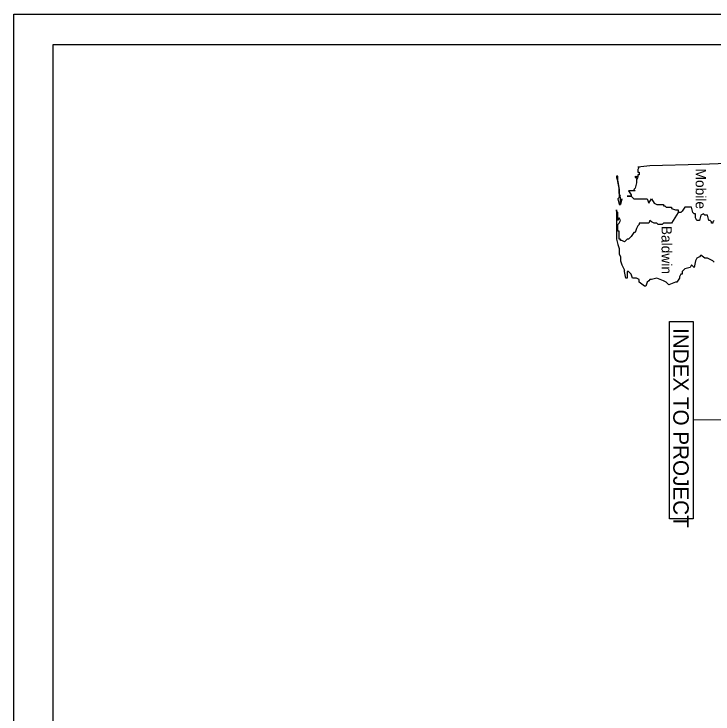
# Model space of a CAD drawing. Extents: x 0 to 0.917, y 0 to 0.708.
# Drawn here: x 0 to 0.3538, y 0.3542 to 0.7083 of the extents above; entities that cross this region are included whole.
import ezdxf

# ---------------------------------------------------------------- set-up
doc = ezdxf.new("R2010")
doc.units = 0
for name, color, linetype in [('ANNO-SHT', 7, 'Continuous'), ('ANNO-TXT', 7, 'Continuous'), ('SHT-BDR', 7, 'Continuous'), ('SHT-FENCE', 7, 'Continuous')]:
    doc.layers.add(name, color=color, linetype=linetype)

msp = doc.modelspace()

# ---------------------------------------------------------------- linework, layer by layer
at = {"layer": 'ANNO-SHT'}
msp.add_line((0.44418, 0.5033), (0.34372, 0.50284), dxfattribs=at)
for points in [[(0.31583, 0.63102), (0.31583, 0.63102), (0.31651, 0.63102), (0.31651, 0.63102), (0.31583, 0.62967), (0.31583, 0.62831), (0.31583, 0.62831), (0.31651, 0.62831), (0.31651, 0.62831), (0.31651, 0.62831), (0.31651, 0.62763), (0.31651, 0.62695), (0.31651, 0.62695), (0.31651, 0.62695), (0.31583, 0.62695), (0.31583, 0.62627), (0.31583, 0.62559), (0.31516, 0.62627), (0.31516, 0.62559), (0.31516, 0.62559), (0.31448, 0.62627), (0.31448, 0.62559), (0.31448, 0.62559), (0.31516, 0.62559), (0.31583, 0.62492), (0.31516, 0.62492), (0.31516, 0.62424), (0.31516, 0.62356), (0.31516, 0.62356), (0.31516, 0.62288), (0.31448, 0.62016), (0.3138, 0.61949), (0.31448, 0.61881), (0.31448, 0.61881), (0.31313, 0.61881), (0.31313, 0.61881), (0.31313, 0.61881), (0.31245, 0.61881), (0.3111, 0.61881), (0.3111, 0.61881), (0.31245, 0.61677), (0.31245, 0.61609), (0.3111, 0.61609), (0.31042, 0.61609), (0.31042, 0.61609), (0.31245, 0.61609), (0.3138, 0.61474), (0.31516, 0.61474), (0.31583, 0.61474), (0.31651, 0.61474), (0.32057, 0.61474), (0.32125, 0.6127), (0.3226, 0.61474), (0.32395, 0.6127), (0.32531, 0.61202), (0.32531, 0.61202), (0.32598, 0.61202), (0.32801, 0.61202), (0.32869, 0.61202), (0.32869, 0.61202), (0.32869, 0.61134), (0.32937, 0.61134), (0.33004, 0.61066), (0.33072, 0.61066), (0.33072, 0.61066), (0.3314, 0.61066), (0.33207, 0.61066), (0.33275, 0.61066), (0.33275, 0.61066), (0.33275, 0.61066), (0.33275, 0.60998), (0.33478, 0.60931), (0.33546, 0.60931), (0.33546, 0.60931), (0.33613, 0.60931), (0.33613, 0.60795)], [(0.31583, 0.63102), (0.32192, 0.6317), (0.32192, 0.6317), (0.34764, 0.63238), (0.36523, 0.63306)], [(0.30568, 0.62627), (0.30501, 0.62627), (0.30501, 0.62559), (0.30501, 0.62559), (0.30501, 0.62559), (0.30568, 0.62356), (0.30636, 0.61949), (0.30636, 0.61745), (0.30636, 0.61609), (0.30636, 0.61541), (0.30568, 0.61474), (0.30636, 0.61202), (0.30636, 0.61202), (0.30636, 0.61202), (0.30636, 0.61202), (0.30704, 0.61202), (0.30771, 0.61474), (0.30771, 0.61474), (0.30704, 0.61202), (0.30636, 0.61202), (0.30704, 0.6127), (0.30704, 0.61474), (0.30704, 0.61474), (0.30704, 0.61474), (0.30704, 0.61474), (0.30704, 0.61474), (0.30704, 0.61541), (0.30704, 0.61541), (0.30636, 0.61609), (0.30704, 0.61609), (0.30636, 0.61745), (0.30636, 0.61745), (0.30636, 0.62016), (0.30568, 0.62356), (0.30568, 0.62559), (0.30568, 0.62559), (0.30568, 0.62627)], [(0.30501, 0.60931), (0.30501, 0.60659), (0.30501, 0.6032), (0.30501, 0.60116), (0.30501, 0.59777), (0.30501, 0.59437), (0.30568, 0.59166), (0.30636, 0.58962), (0.30636, 0.58691), (0.30704, 0.58555), (0.30704, 0.58351), (0.30771, 0.58148), (0.30771, 0.58148), (0.30771, 0.58148), (0.30771, 0.58148), (0.30907, 0.57876)], [(0.33613, 0.60795), (0.33275, 0.60252), (0.33207, 0.60252), (0.3314, 0.60252), (0.3314, 0.60252), (0.32937, 0.60252), (0.32869, 0.60252), (0.32801, 0.60184), (0.32598, 0.60184), (0.32531, 0.60252), (0.32395, 0.60252), (0.3226, 0.6032), (0.32192, 0.60388), (0.32125, 0.60252), (0.31989, 0.60252), (0.31651, 0.60252), (0.31651, 0.60184), (0.31583, 0.60116), (0.31516, 0.5998), (0.31448, 0.59777), (0.31448, 0.59777), (0.3138, 0.59777), (0.31245, 0.59573), (0.3111, 0.59437), (0.31042, 0.59437), (0.30907, 0.59302), (0.30907, 0.59302), (0.30907, 0.59302), (0.30771, 0.59369), (0.30704, 0.59369), (0.30704, 0.59437), (0.30704, 0.59437), (0.30636, 0.59437), (0.30636, 0.59505), (0.30636, 0.59573), (0.30636, 0.59641), (0.30636, 0.59777), (0.30636, 0.59777), (0.30636, 0.59777), (0.30636, 0.59845), (0.30568, 0.59845), (0.30568, 0.5998), (0.30568, 0.60048), (0.30568, 0.60116), (0.30568, 0.60184), (0.30636, 0.60252), (0.30636, 0.60252), (0.30704, 0.60388), (0.30704, 0.60388), (0.30636, 0.60523), (0.30636, 0.60523), (0.30568, 0.60388), (0.30568, 0.60523), (0.30568, 0.60523), (0.30568, 0.60659), (0.30568, 0.60659), (0.30568, 0.60659), (0.30568, 0.60795), (0.30501, 0.60863), (0.30501, 0.60931), (0.30501, 0.60931), (0.30501, 0.60931), (0.30501, 0.60931)], [(0.3544, 0.60388), (0.35373, 0.6032), (0.35373, 0.60252), (0.35305, 0.60252), (0.35305, 0.6032), (0.35237, 0.60388), (0.3517, 0.60388), (0.3517, 0.60388), (0.35102, 0.60659), (0.34967, 0.60659), (0.34899, 0.60727), (0.34764, 0.60659), (0.34696, 0.60388), (0.34628, 0.60388), (0.34561, 0.60388), (0.34493, 0.60523), (0.34493, 0.60659), (0.34493, 0.60727), (0.34425, 0.60727), (0.34358, 0.60795), (0.34358, 0.60795), (0.3429, 0.61066), (0.3429, 0.61066), (0.34222, 0.61066), (0.34019, 0.61066), (0.34019, 0.61066), (0.33952, 0.61066), (0.33816, 0.60863), (0.33749, 0.60795), (0.33681, 0.60795), (0.33613, 0.60795), (0.33613, 0.60795)], [(0.3544, 0.58284), (0.35373, 0.58351), (0.35102, 0.58487), (0.34967, 0.58487), (0.34764, 0.58623), (0.34696, 0.58555), (0.34696, 0.58555), (0.34561, 0.58487), (0.34493, 0.58351), (0.34425, 0.58012), (0.3429, 0.58148), (0.34222, 0.58012), (0.33952, 0.57944), (0.33884, 0.57876), (0.33816, 0.57808), (0.33816, 0.57673), (0.33749, 0.57673), (0.33681, 0.57537), (0.33681, 0.57469), (0.33546, 0.57265), (0.33478, 0.57265), (0.3314, 0.5713), (0.33004, 0.57265), (0.32869, 0.57333), (0.32531, 0.57469), (0.3226, 0.57401), (0.32192, 0.57401), (0.32125, 0.57333), (0.32057, 0.57265), (0.31989, 0.57062), (0.31922, 0.57062), (0.31651, 0.57265), (0.31651, 0.57401), (0.31516, 0.57469), (0.31313, 0.57469), (0.31245, 0.57673), (0.3111, 0.57808), (0.31042, 0.57808), (0.31042, 0.57469), (0.30974, 0.57469), (0.30907, 0.57808), (0.30907, 0.57876), (0.30907, 0.57876), (0.30907, 0.57876)]]:
    msp.add_lwpolyline(points, dxfattribs=at)
msp.add_lwpolyline([(0.34372, 0.55283), (0.34372, 0.45283), (0.33172, 0.45283), (0.33172, 0.55283)], close=True, dxfattribs=at)
at = {"layer": 'SHT-BDR'}
msp.add_lwpolyline([(0.01986, 0.69298), (0.89679, 0.69298), (0.89679, 0.01536), (0.01986, 0.01536)], close=True, dxfattribs=at)
at = {"layer": 'SHT-FENCE'}
msp.add_lwpolyline([(0, 0.70833), (0.91666, 0.70833), (0.91666, 0), (0, 0)], close=True, dxfattribs=at)

# ---------------------------------------------------------------- texts
at = {"layer": 'ANNO-TXT'}
for s, height, p in [('Mobile', 0.005208, (0.34503, 0.63016)), ('Baldwin', 0.005208, (0.32775, 0.60117)), ('INDEX TO PROJECT', 0.0078125, (0.3337, 0.54942))]:
    msp.add_text(s, height=height, rotation=270, dxfattribs=at).set_placement(p)

doc.saveas('drawing.dxf')
